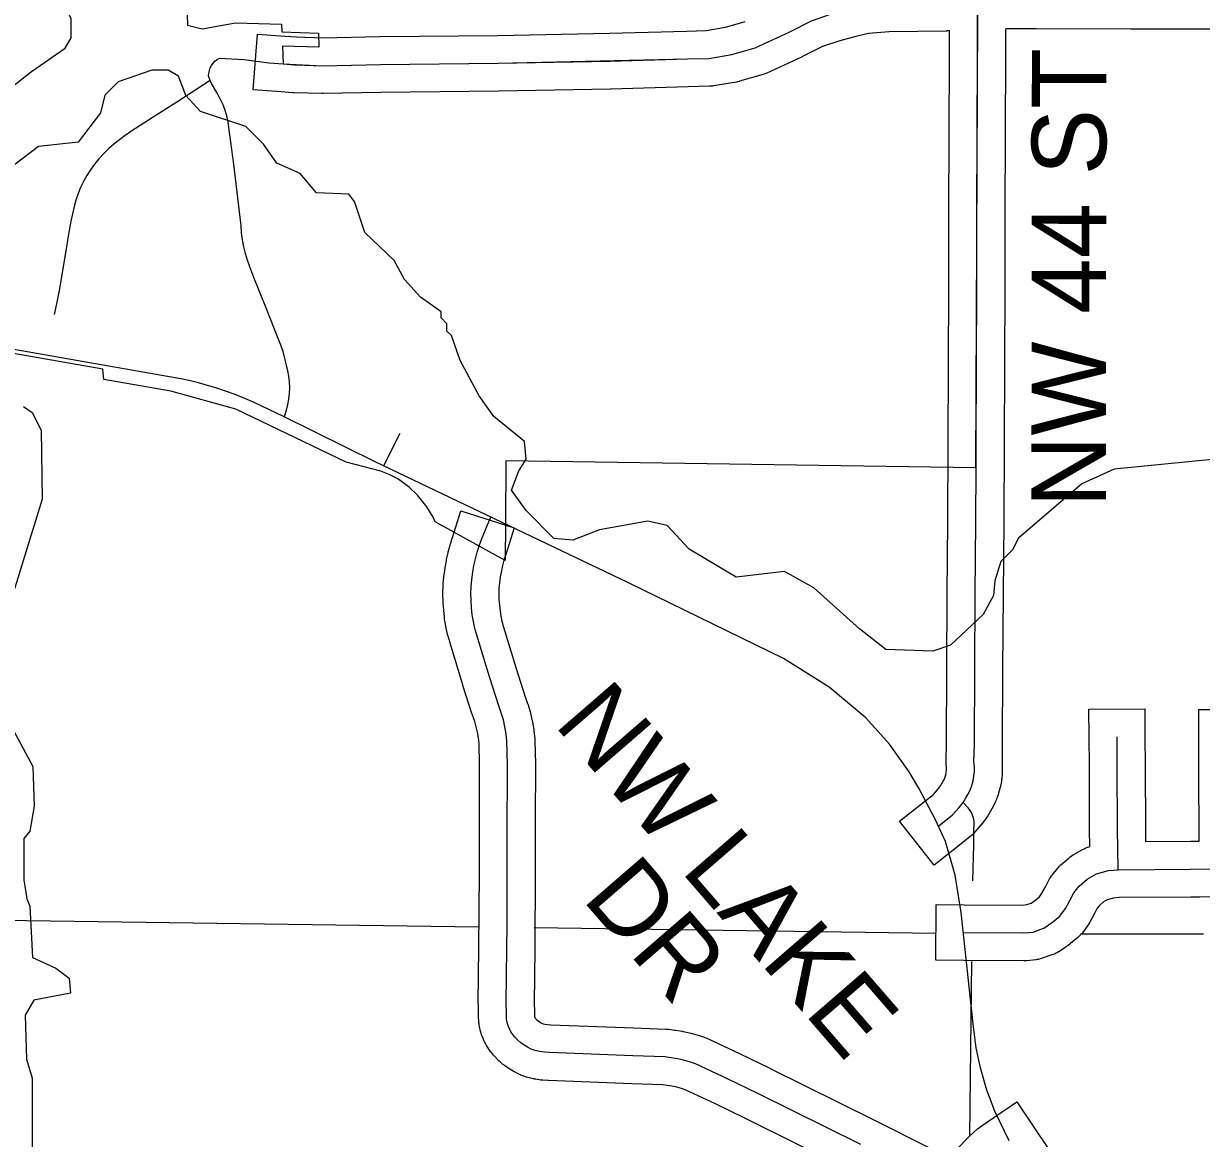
# Model space of a CAD drawing. Extents: x -1403959 to 81668, y -1400582 to 11018.
# Drawn here: x 6804.9 to 6927.2, y 9282.2 to 9398 of the extents above; entities that cross this region are included whole.
import ezdxf

# ---------------------------------------------------------------- set-up
doc = ezdxf.new("R2010")
doc.units = 0
for name, color, linetype in [('tdCiCityDivCarto', 7, 'Continuous'), ('tdCiCoBndryTxt', 7, 'Continuous'), ('tdCiHydroTxt', 7, 'Continuous'), ('tdCiMapFrame', 7, 'Continuous'), ('tdCiRRCL', 7, 'Continuous'), ('tdCiRROwnerTxt', 7, 'Continuous'), ('tdCiSectLine', 7, 'Continuous'), ('tdCiSectNmbr', 7, 'Continuous'), ('tdCiSectTwpRng', 7, 'Continuous'), ('tdCoCityStreetMajor', 7, 'Continuous'), ('tdCoSecRteCL', 7, 'Continuous'), ('tdCoSectNmbr', 7, 'Continuous'), ('tdCoSurfBitum', 7, 'Continuous')]:
    doc.layers.add(name, color=color, linetype=linetype)

msp = doc.modelspace()

# ---------------------------------------------------------------- linework, layer by layer
at = {"layer": 'tdCiCityDivCarto'}
msp.add_lwpolyline([(6903.5, 9308.97), (6903.6, 9312.73), (6903.61, 9314.43), (6903.64, 9314.75), (6903.63, 9315.08), (6903.58, 9315.4), (6903.5, 9315.71), (6903.37, 9316.01), (6903.21, 9316.29), (6903.02, 9316.56), (6902.48, 9317.14)], dxfattribs=at)
at = {"layer": 'tdCiCoBndryTxt'}
for points in [[(6903.83, 9351.93), (6903.85, 9354.45), (6903.86, 9362.57), (6903.9, 9370.69), (6903.91, 9378.4), (6903.94, 9386.44), (6903.98, 9394.89), (6903.99, 9399.08), (6903.97, 9400.3)], [(6899.95, 9314.7), (6901.39, 9315.83), (6902.07, 9316.59), (6902.48, 9317.14), (6902.55, 9317.23), (6902.72, 9317.53), (6902.98, 9317.96), (6903.2, 9318.41), (6903.37, 9318.88), (6903.51, 9319.36), (6903.6, 9319.85), (6903.65, 9320.35), (6903.65, 9320.85), (6903.61, 9321.35), (6903.65, 9323.17), (6903.68, 9330.94), (6903.73, 9338.76), (6903.79, 9346.3), (6903.83, 9351.9)], [(6903.83, 9351.9), (6903.83, 9351.93)], [(6852.46, 9332.9), (6851.97, 9334.51), (6851.77, 9335.21), (6851.61, 9335.91), (6851.5, 9336.63), (6851.43, 9337.35), (6851.37, 9338.09), (6851.35, 9338.83), (6851.37, 9339.56), (6851.44, 9340.3), (6851.55, 9341.03), (6851.67, 9341.73), (6851.82, 9342.42), (6852, 9343.11), (6852.2, 9343.76)], [(6855.11, 9304.41), (6855.14, 9309.82), (6855.14, 9315.23), (6855.15, 9319.39), (6855.16, 9321.05), (6855.1, 9323.48), (6855.02, 9324.23), (6854.89, 9324.98), (6854.73, 9325.72), (6854.51, 9326.45), (6854.26, 9327.16), (6853.29, 9330.18), (6852.46, 9332.9)], [(6891.84, 9281.59), (6881.15, 9286.91), (6878, 9288.43), (6874.69, 9289.99), (6874.07, 9290.19), (6873.44, 9290.36), (6872.8, 9290.5), (6872.16, 9290.61), (6871.51, 9290.69), (6868.19, 9290.81), (6859.52, 9291.15), (6859.01, 9291.18), (6858.51, 9291.25), (6858.02, 9291.35), (6857.63, 9291.51), (6857.25, 9291.7), (6856.89, 9291.92), (6856.55, 9292.16), (6856.23, 9292.44), (6855.93, 9292.74), (6855.71, 9293.01), (6855.51, 9293.3), (6855.35, 9293.61), (6855.22, 9293.93), (6855.13, 9294.27), (6855.07, 9294.61), (6855.05, 9294.96), (6855.07, 9295.31), (6855.02, 9296.23), (6855.1, 9301.97), (6855.11, 9304.41)]]:
    msp.add_lwpolyline(points, dxfattribs=at)
at = {"layer": 'tdCiHydroTxt'}
msp.add_lwpolyline([(6824.27, 9392.11), (6820.82, 9389.87), (6818.34, 9388.31), (6816.05, 9386.81), (6815.44, 9386.4), (6814.85, 9385.96), (6814.27, 9385.5), (6813.72, 9385.01), (6813.2, 9384.49), (6812.72, 9383.97), (6812.27, 9383.42), (6811.85, 9382.85), (6811.47, 9382.26), (6811.12, 9381.64), (6810.81, 9381.01), (6810.55, 9380.36), (6810.33, 9379.69), (6810.15, 9379.01), (6809.82, 9377.49), (6809.54, 9375.96), (6809.29, 9374.43), (6808.96, 9372.58), (6808.62, 9370.49), (6808.32, 9368.91), (6808.08, 9367.82)], dxfattribs=at)
at = {"layer": 'tdCiMapFrame'}
msp.add_lwpolyline([(6831.86, 9393.83), (6833.08, 9393.74), (6835.96, 9393.65), (6841.96, 9393.77), (6854.18, 9393.9), (6865.82, 9394.12), (6873.85, 9394.35), (6876.06, 9394.41), (6878.46, 9394.81), (6880.88, 9395.52), (6884.48, 9397.17), (6886.73, 9398.31), (6888.81, 9399.03), (6890.67, 9399.52), (6892.21, 9399.86), (6894.65, 9400.06), (6900.71, 9400.16), (6902.76, 9400.22), (6903.43, 9400.2), (6903.97, 9400.3)], dxfattribs=at)
at = {"layer": 'tdCiRRCL'}
for points in [[(6903.99, 9399.08), (6903.83, 9367.47), (6903.76, 9351.9), (6854.97, 9352.62), (6854.94, 9346.1), (6854.92, 9342.25), (6852.2, 9343.76), (6847.64, 9346.29), (6847.44, 9346.76), (6846.79, 9347.82), (6845.81, 9349.06), (6844.93, 9349.89), (6843.78, 9350.75), (6842.88, 9351.18), (6842, 9351.52), (6838.39, 9352.48), (6826.95, 9357.99), (6820.18, 9359.86), (6813.23, 9361.07), (6813.14, 9362.13), (6798.47, 9364.69)], [(6821.9, 9398.98), (6821.93, 9397.85), (6823.43, 9397.48), (6826.91, 9398.11), (6831.69, 9397.96), (6831.72, 9397.16), (6835.52, 9397.04), (6835.58, 9395.57), (6831.78, 9395.69), (6831.86, 9393.83), (6835.96, 9393.65), (6841.96, 9393.77), (6854.18, 9393.9), (6873.85, 9394.35), (6876.06, 9394.41), (6878.46, 9394.81), (6880.88, 9395.52), (6884.48, 9397.17), (6886.73, 9398.31)]]:
    msp.add_lwpolyline(points, dxfattribs=at)
at = {"layer": 'tdCiRROwnerTxt'}
for points in [[(6918.47, 9323.84), (6918.47, 9323.93)], [(6918.57, 9310.22), (6918.52, 9314.34), (6918.49, 9320.95), (6918.47, 9323.84)], [(6910.55, 9303.96), (6910.85, 9304.07), (6911.78, 9304.7), (6912.53, 9305.32), (6913.13, 9306.13), (6913.57, 9306.96), (6913.97, 9307.74), (6914.55, 9308.45), (6915.37, 9309.17), (6916.32, 9309.72), (6917.58, 9310.05), (6918.57, 9310.14), (6926.11, 9310.2), (6929.93, 9310.22), (6934.81, 9310.19), (6941.28, 9310.22), (6951.53, 9310.21)], [(6918.57, 9310.14), (6918.57, 9310.22)], [(6902.57, 9303.61), (6908.8, 9303.57), (6909.74, 9303.67), (6910.55, 9303.96)]]:
    msp.add_lwpolyline(points, dxfattribs=at)
at = {"layer": 'tdCiSectLine'}
for points in [[(6930.53, 9397.45), (6919.88, 9397.44), (6919.87, 9397.44), (6919.86, 9397.44), (6910.07, 9397.48), (6906.91, 9397.48), (6906.92, 9397.44), (6906.88, 9397.44), (6906.88, 9394.89), (6906.88, 9394.88), (6906.84, 9386.43), (6906.81, 9378.39), (6906.81, 9370.69), (6906.81, 9370.67), (6906.77, 9362.56), (6906.75, 9354.44), (6906.75, 9354.43), (6906.7, 9346.28), (6906.7, 9346.27), (6906.63, 9338.74), (6906.58, 9330.93), (6906.55, 9323.16), (6906.55, 9323.11), (6906.52, 9321.43), (6906.54, 9321.08), (6906.55, 9321.04), (6906.55, 9320.85), (6906.55, 9320.83), (6906.55, 9320.33), (6906.54, 9320.16), (6906.54, 9320.07), (6906.49, 9319.57), (6906.48, 9319.47), (6906.45, 9319.32), (6906.36, 9318.83), (6906.36, 9318.79), (6906.31, 9318.61), (6906.3, 9318.58), (6906.17, 9318.1), (6906.12, 9317.94), (6906.09, 9317.85), (6905.91, 9317.38), (6905.88, 9317.3), (6905.81, 9317.15), (6905.6, 9316.7), (6905.58, 9316.67), (6905.49, 9316.51), (6905.47, 9316.47), (6905.04, 9315.74), (6904.96, 9315.61), (6904.87, 9315.48), (6904.39, 9314.85), (6904.37, 9314.83), (6904.25, 9314.68), (6904.23, 9314.66), (6903.56, 9313.9), (6903.44, 9313.78), (6903.3, 9313.65), (6903.19, 9313.55), (6901.75, 9312.42), (6899.47, 9310.62), (6895.88, 9315.18), (6898.16, 9316.98), (6899.4, 9317.95), (6899.82, 9318.43), (6900.13, 9318.84), (6900.42, 9319.33), (6900.53, 9319.55), (6900.61, 9319.78), (6900.68, 9320.01), (6900.72, 9320.25), (6900.75, 9320.5), (6900.75, 9320.74), (6900.72, 9321.11), (6900.72, 9321.16), (6900.71, 9321.35), (6900.71, 9321.41), (6900.75, 9323.21), (6900.78, 9330.95), (6900.78, 9330.96), (6900.83, 9338.78), (6900.83, 9338.79), (6900.89, 9346.32), (6900.94, 9354.46), (6900.96, 9362.57), (6900.96, 9362.58), (6901, 9370.7), (6901.01, 9378.4), (6901.01, 9378.41), (6901.03, 9386.45), (6901.03, 9386.45), (6901.08, 9394.9), (6901.08, 9397.26), (6900.8, 9397.26), (6900.75, 9397.25), (6894.79, 9397.16), (6892.65, 9396.99), (6891.35, 9396.7), (6889.66, 9396.25), (6887.86, 9395.64), (6885.79, 9394.59), (6885.76, 9394.57), (6885.69, 9394.54), (6882.09, 9392.89), (6881.99, 9392.84), (6881.82, 9392.77), (6881.7, 9392.74), (6879.27, 9392.03), (6879.21, 9392.01), (6879.03, 9391.97), (6878.94, 9391.95), (6876.54, 9391.55), (6876.44, 9391.54), (6876.25, 9391.52), (6876.15, 9391.51), (6873.94, 9391.45), (6873.93, 9391.45), (6865.9, 9391.22), (6865.87, 9391.22), (6854.24, 9391), (6854.22, 9391), (6842, 9390.87), (6836.02, 9390.75), (6835.96, 9390.75), (6835.87, 9390.75), (6832.99, 9390.84), (6832.89, 9390.84), (6832.86, 9390.84), (6831.65, 9390.93), (6828.75, 9391.15), (6829.19, 9396.94), (6832.08, 9396.72), (6833.23, 9396.64), (6835.98, 9396.55), (6841.9, 9396.67), (6841.93, 9396.67), (6854.14, 9396.8), (6865.75, 9397.02), (6873.77, 9397.25), (6875.78, 9397.31), (6877.81, 9397.65), (6879.86, 9398.25)], [(6890.54, 9278.99), (6879.87, 9284.31), (6876.76, 9285.81), (6873.62, 9287.28), (6873.24, 9287.41), (6872.75, 9287.54), (6872.24, 9287.65), (6871.74, 9287.74), (6871.28, 9287.8), (6868.08, 9287.91), (6868.07, 9287.91), (6859.4, 9288.25), (6859.34, 9288.25), (6858.83, 9288.28), (6858.82, 9288.28), (6858.63, 9288.3), (6858.61, 9288.3), (6858.11, 9288.37), (6857.95, 9288.4), (6857.89, 9288.41), (6857.4, 9288.52), (6857.27, 9288.55), (6857.09, 9288.61), (6856.95, 9288.66), (6856.56, 9288.81), (6856.52, 9288.83), (6856.34, 9288.91), (6856.34, 9288.91), (6855.96, 9289.1), (6855.8, 9289.18), (6855.75, 9289.21), (6855.39, 9289.43), (6855.28, 9289.5), (6855.18, 9289.57), (6854.84, 9289.81), (6854.78, 9289.86), (6854.65, 9289.96), (6854.33, 9290.24), (6854.31, 9290.26), (6854.17, 9290.39), (6854.16, 9290.41), (6853.86, 9290.71), (6853.75, 9290.83), (6853.71, 9290.87), (6853.48, 9291.14), (6853.4, 9291.24), (6853.3, 9291.39), (6853.1, 9291.68), (6853.1, 9291.69), (6853, 9291.85), (6852.94, 9291.95), (6852.78, 9292.26), (6852.75, 9292.32), (6852.67, 9292.5), (6852.65, 9292.54), (6852.52, 9292.86), (6852.47, 9293), (6852.42, 9293.16), (6852.33, 9293.49), (6852.33, 9293.52), (6852.28, 9293.7), (6852.26, 9293.8), (6852.21, 9294.14), (6852.19, 9294.23), (6852.18, 9294.42), (6852.17, 9294.45), (6852.15, 9294.8), (6852.15, 9294.96), (6852.15, 9295.11), (6852.16, 9295.31), (6852.13, 9296.09), (6852.12, 9296.23), (6852.12, 9296.27), (6852.19, 9302), (6852.24, 9309.83), (6852.24, 9315.23), (6852.24, 9315.24), (6852.26, 9321.02), (6852.2, 9323.29), (6852.14, 9323.85), (6852.04, 9324.42), (6851.92, 9324.99), (6851.75, 9325.55), (6851.53, 9326.19), (6851.51, 9326.23), (6851.5, 9326.27), (6850.53, 9329.29), (6850.52, 9329.33), (6849.2, 9333.67), (6849.19, 9333.69), (6848.98, 9334.39), (6848.97, 9334.46), (6848.94, 9334.57), (6848.78, 9335.28), (6848.76, 9335.35), (6848.74, 9335.47), (6848.63, 9336.18), (6848.62, 9336.25), (6848.61, 9336.37), (6848.54, 9337.09), (6848.54, 9337.1), (6848.48, 9337.84), (6848.47, 9337.9), (6848.47, 9338.01), (6848.45, 9338.75), (6848.45, 9338.83), (6848.45, 9338.92), (6848.47, 9339.66), (6848.48, 9339.75), (6848.48, 9339.83), (6848.55, 9340.56), (6848.56, 9340.68), (6848.57, 9340.73), (6848.68, 9341.46), (6848.69, 9341.51), (6848.81, 9342.21), (6848.82, 9342.3), (6848.83, 9342.35), (6848.98, 9343.04), (6849.01, 9343.17), (6849.2, 9343.86), (6849.2, 9343.86), (6849.23, 9343.99), (6849.44, 9344.63), (6850.31, 9347.4), (6855.84, 9345.65), (6854.97, 9342.88), (6854.79, 9342.3), (6854.64, 9341.74), (6854.52, 9341.18), (6854.41, 9340.57), (6854.32, 9339.95), (6854.27, 9339.39), (6854.25, 9338.82), (6854.27, 9338.25), (6854.32, 9337.61), (6854.38, 9336.98), (6854.46, 9336.46), (6854.58, 9335.94), (6854.75, 9335.34), (6856.06, 9331.04), (6857.01, 9328.09), (6857.25, 9327.42), (6857.26, 9327.38), (6857.3, 9327.26), (6857.51, 9326.53), (6857.53, 9326.47), (6857.56, 9326.36), (6857.72, 9325.62), (6857.74, 9325.55), (6857.76, 9325.45), (6857.88, 9324.7), (6857.89, 9324.61), (6857.9, 9324.53), (6857.98, 9323.78), (6857.99, 9323.67), (6858, 9323.56), (6858.06, 9321.13), (6858.06, 9321.05), (6858.06, 9321.04), (6858.04, 9315.23), (6858.04, 9309.82), (6858.04, 9309.81), (6858, 9301.96), (6858, 9301.94), (6857.93, 9296.28), (6857.97, 9295.45), (6857.97, 9295.31), (6857.97, 9295.16), (6857.96, 9294.97), (6857.96, 9294.93), (6857.97, 9294.89), (6857.98, 9294.85), (6857.99, 9294.82), (6858.01, 9294.78), (6858.03, 9294.75), (6858.08, 9294.69), (6858.21, 9294.56), (6858.35, 9294.44), (6858.49, 9294.34), (6858.65, 9294.24), (6858.81, 9294.16), (6858.87, 9294.14), (6859.02, 9294.11), (6859.3, 9294.07), (6859.66, 9294.04), (6868.29, 9293.71), (6871.61, 9293.59), (6871.7, 9293.59), (6871.87, 9293.57), (6872.52, 9293.49), (6872.54, 9293.49), (6872.65, 9293.47), (6873.3, 9293.36), (6873.37, 9293.35), (6873.43, 9293.33), (6874.07, 9293.19), (6874.19, 9293.16), (6874.2, 9293.16), (6874.83, 9292.99), (6874.96, 9292.95), (6875.59, 9292.75), (6875.63, 9292.73), (6875.8, 9292.67), (6875.93, 9292.61), (6879.24, 9291.05), (6879.26, 9291.04), (6882.41, 9289.53), (6882.43, 9289.51), (6882.44, 9289.51), (6893.13, 9284.19), (6893.14, 9284.19), (6899.07, 9281.23)], [(6908.8, 9300.67), (6908.78, 9300.67), (6902.56, 9300.71), (6899.65, 9300.73), (6899.69, 9306.53), (6902.59, 9306.51), (6908.65, 9306.47), (6909.09, 9306.52), (6909.54, 9306.68), (6910.04, 9307.02), (6910.4, 9307.32), (6910.67, 9307.69), (6911, 9308.3), (6911.37, 9309.04), (6911.45, 9309.19), (6911.55, 9309.35), (6911.66, 9309.51), (6911.72, 9309.58), (6912.31, 9310.3), (6912.37, 9310.37), (6912.5, 9310.51), (6912.64, 9310.64), (6912.64, 9310.64), (6913.46, 9311.35), (6913.6, 9311.47), (6913.75, 9311.58), (6913.91, 9311.68), (6914.87, 9312.23), (6914.87, 9312.23), (6915.04, 9312.32), (6915.21, 9312.4), (6915.39, 9312.47), (6915.57, 9312.52), (6915.58, 9312.52), (6915.64, 9312.54), (6915.61, 9314.3), (6915.61, 9314.33), (6915.59, 9320.93), (6915.57, 9323.9), (6915.54, 9326.81), (6921.35, 9326.85), (6921.37, 9323.95), (6921.39, 9320.97), (6921.39, 9320.96), (6921.42, 9314.36), (6921.44, 9313.07), (6926.09, 9313.1), (6926.09, 9313.1), (6927, 9313.11), (6926.98, 9314.27), (6926.98, 9314.29), (6926.96, 9319.44), (6926.96, 9319.45), (6926.96, 9323.88), (6926.96, 9326.78), (6932.77, 9326.78)], [(6929.94, 9307.32), (6927.07, 9307.29), (6927.07, 9307.3), (6926.13, 9307.3), (6918.72, 9307.24), (6918.09, 9307.18), (6917.44, 9307.01), (6917.06, 9306.79), (6916.64, 9306.43), (6916.41, 9306.15), (6916.17, 9305.66), (6916.13, 9305.58), (6915.68, 9304.75), (6915.64, 9304.68), (6915.54, 9304.52), (6915.47, 9304.42), (6914.87, 9303.6), (6914.83, 9303.55), (6914.71, 9303.4), (6914.58, 9303.27), (6914.44, 9303.14), (6914.38, 9303.09), (6913.64, 9302.47), (6913.55, 9302.4), (6913.41, 9302.3), (6912.48, 9301.66), (6912.46, 9301.65), (6912.3, 9301.55), (6912.14, 9301.46), (6911.96, 9301.38), (6911.81, 9301.33), (6910.7, 9300.94), (6910.67, 9300.93), (6910.49, 9300.87), (6910.3, 9300.83), (6910.12, 9300.8), (6910.05, 9300.79), (6909.11, 9300.69), (6908.99, 9300.68), (6908.8, 9300.67)], [(6901.97, 9281.25), (6902.94, 9282.26), (6902.98, 9282.31), (6903.08, 9282.4), (6904.01, 9283.25), (6904.05, 9283.28), (6904.2, 9283.41), (6904.34, 9283.51), (6905.66, 9284.4), (6908.07, 9286.02), (6911.31, 9281.2)]]:
    msp.add_lwpolyline(points, dxfattribs=at)
at = {"layer": 'tdCiSectNmbr'}
for points in [[(6827.54, 9376.31), (6827.49, 9377.02), (6826.75, 9383.41), (6826.22, 9387.22), (6826.13, 9387.83), (6825.99, 9388.43), (6825.82, 9389.01), (6825.61, 9389.59), (6825.36, 9390.15), (6825.07, 9390.69), (6824.43, 9391.81), (6824.27, 9392.11), (6824.12, 9392.61), (6824.13, 9392.89), (6824.19, 9393.16), (6824.28, 9393.43), (6824.41, 9393.68), (6824.58, 9393.91), (6824.77, 9394.11), (6824.99, 9394.29), (6825.23, 9394.43), (6827.78, 9394.3), (6830.4, 9393.94), (6831.86, 9393.83)], [(6831.48, 9364.97), (6831.35, 9365.3), (6830.12, 9368.39), (6828.8, 9371.66), (6828.4, 9372.77), (6828.14, 9373.45), (6827.93, 9374.15), (6827.76, 9374.85), (6827.63, 9375.57), (6827.54, 9376.29), (6827.54, 9376.31)], [(6832, 9357.21), (6832.22, 9357.87), (6832.36, 9358.45), (6832.46, 9359.03), (6832.52, 9359.62), (6832.54, 9360.21), (6832.51, 9360.8), (6832.44, 9361.39), (6832.34, 9361.97), (6832.19, 9362.54), (6832.04, 9363.25), (6831.85, 9363.95), (6831.62, 9364.63), (6831.48, 9364.97)], [(6852.2, 9343.76), (6852.21, 9343.79), (6852.46, 9344.45), (6853.08, 9345.96), (6853.45, 9346.82)]]:
    msp.add_lwpolyline(points, dxfattribs=at)
at = {"layer": 'tdCiSectTwpRng'}
msp.add_lwpolyline([(6842.3, 9352.11), (6844.02, 9355.49)], dxfattribs=at)
at = {"layer": 'tdCoCityStreetMajor'}
for points in [[(6802.74, 9304.91), (6852.15, 9304.22)], [(6857.94, 9304.14), (6899.64, 9303.56)], [(6914.67, 9303.49), (6927.45, 9303.47)], [(6903.18, 9282.47), (6903.4, 9300.61)]]:
    msp.add_lwpolyline(points, dxfattribs=at)
at = {"layer": 'tdCoSecRteCL'}
msp.add_lwpolyline([(6907.25, 9281.99), (6905.77, 9285.08), (6904.96, 9287.24), (6904.27, 9289.55), (6903.85, 9291.64), (6903.53, 9294.12), (6902.29, 9305.71), (6901.64, 9309.59), (6900.64, 9313.07), (6899.61, 9315.33), (6897.88, 9318.61), (6896.86, 9320.3), (6894.84, 9323.18), (6892.36, 9325.93), (6888.58, 9329.09), (6883.84, 9332.07), (6867.67, 9339.99), (6841.49, 9352.48), (6831.9, 9357.2), (6828.86, 9358.66), (6827.87, 9359.08), (6826.88, 9359.49), (6825.86, 9359.85), (6824.88, 9360.18), (6823.99, 9360.45), (6823.05, 9360.72), (6822.22, 9360.92), (6821.23, 9361.13), (6771.33, 9369.9)], dxfattribs=at)
at = {"layer": 'tdCoSurfBitum'}
for points in [[(6803.86, 9383.28), (6802.64, 9384.96), (6802.49, 9385.88), (6802.19, 9386.49), (6801.89, 9389.24), (6802.81, 9390.76), (6805.71, 9393.05), (6809.23, 9395.48), (6809.84, 9396.55), (6809.85, 9398.53), (6807.41, 9403.43), (6805.89, 9405.11), (6803.6, 9405.57), (6802.68, 9405.27), (6799.02, 9405.28)], [(6928.71, 9352.77), (6918.17, 9351.73), (6914.81, 9350.21), (6908.23, 9344.58), (6907.61, 9343.36), (6906.39, 9342.14), (6905.78, 9340.15), (6905.62, 9338.63), (6904.55, 9336.65), (6901.18, 9333.45), (6899.35, 9332.84), (6894.46, 9333), (6891.72, 9335.15), (6886.99, 9339.43), (6883.94, 9341.12), (6878.9, 9340.52), (6874.02, 9343.43), (6871.74, 9345.88), (6869.75, 9346.34), (6864.71, 9345.44), (6861.96, 9344.37), (6859.97, 9344.53), (6857.08, 9347.44), (6855.56, 9349.58), (6856.32, 9351.56), (6857.09, 9352.78), (6856.94, 9354.61), (6853.74, 9357.22), (6852.22, 9359.36), (6850.24, 9363.03), (6849.33, 9365.62), (6848.87, 9366.08), (6848.87, 9366.85), (6848.26, 9367.46), (6848.26, 9368.07), (6846.13, 9369.6), (6844.45, 9371.44), (6843.39, 9373.42), (6840.34, 9376.33), (6839.28, 9379.54), (6838.67, 9380.3), (6835.31, 9380.46), (6833.63, 9382.45), (6831.19, 9383.53), (6829.82, 9385.51), (6827.99, 9387.35), (6823.26, 9388.89), (6821.74, 9390.57), (6820.98, 9392.56), (6819.91, 9393.17), (6818.23, 9393.17), (6814.72, 9391.96), (6813.34, 9390.59), (6812.88, 9388.76), (6810.58, 9385.71), (6806.46, 9385.26), (6803.86, 9383.28)], [(6804.88, 9358.24), (6805.79, 9357.63), (6806.71, 9355.8), (6806.84, 9348.62), (6803.15, 9336.72)], [(6803.58, 9325.13), (6805.86, 9320.85), (6806.01, 9316.73), (6805.54, 9314.14), (6804.93, 9313.37), (6804.92, 9309.1), (6805.22, 9307.11), (6805.53, 9306.35), (6805.82, 9301.01), (6808.26, 9299.93), (6809.64, 9298.86), (6809.78, 9297.33), (6805.97, 9296.58), (6805.05, 9295.05), (6805.19, 9290.47), (6805.8, 9288.49), (6805.78, 9278.72)]]:
    msp.add_lwpolyline(points, dxfattribs=at)

# ---------------------------------------------------------------- texts
at = {"layer": 'tdCoSectNmbr'}
for s, rotation, p in [('NW 44 ST', 89.9409, (6917.31, 9347.76)), ('NW LAKE', 310.9016, (6859.89, 9325.24)), ('DR', 310.9016, (6862.81, 9307.1))]:
    msp.add_text(s, height=7.738, rotation=rotation, dxfattribs=at).set_placement(p)

doc.saveas('drawing.dxf')
